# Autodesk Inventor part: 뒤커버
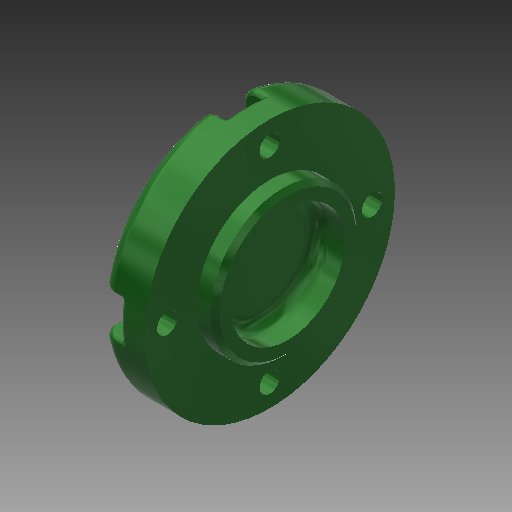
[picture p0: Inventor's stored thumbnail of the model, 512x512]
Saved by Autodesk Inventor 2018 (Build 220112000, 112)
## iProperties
Created: 2015-11
Part Number: 뒤커버
Material: 알루미늄 6061
Document SubType Name: Modeling
Designer: mduedu
Density: 1 g/cm^3
Appearance: 매끄러움 - 짙은 산림 녹색
Author: mduedu
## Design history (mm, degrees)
sketch "스케치1"
  geometry: L1 (-7, 0)-(7, 0); L2 (-7, 0)-(-7, 27.5); L3 (-7, 27.5)-(3, 27.5); L4 (3, 27.5)-(3, 16); L5 (3, 16)-(7, 16); L6 (7, 16)-(7, 0); 2 further points
  constraints: 12 end point, 3 perpendicular, 2 parallel, 1 coincident, 1 horizontal, 1 midpoint
  dimensions: "d0" = 14 distance of L1.start L1.end; "d1" = 55 diameter of L3 L1; "d2" = 4 distance of L4.end L5.end; "d3" = 32 diameter of L5 L1
revolve "회전1" sketch "스케치1" stored, may be unused: angle "d4" = 90 deg
hole "구멍1" diameter "d7" = 25; stored, may be unused: countersink angle "d11" = 90 deg, drill point angle "d13" = 0 deg; dims "d8" = 6, "d9" = 4, "d10" = 2, "d12" = 6, "d61" = 10, "d62" = 10
fillet "모깎기2" dims "d36" = 3
fillet "모깎기3" dims "d37" = 3
sketch "스케치2" dims "d39" = 45
  geometry: C1 r 12.846 at (0, 0) reference; C2 r 24.5 at (0, 0) reference; 6 further points
  constraints: 2 vertical alignment, 1 coincident, 7 other
  dimensions: "d42" = 360 deg dimension on point (0, 0) point (0, 22.5) (derived)
sketch "스케치3"
  geometry: 8 further points
  constraints: 4 coincident
hole "구멍4" sketch "스케치3" at (-22.5, 0), (0, -22.5), (22.5, 0), (0, 22.5) diameter "d44" = 4.5; stored, may be unused: countersink angle "d48" = 90 deg, drill point angle "d50" = 0 deg; dims "d45" = 6, "d46" = 8, "d47" = 4.6, "d49" = 8
sketch "스케치4"
  geometry: L1 (-4, 0)-(-4, -4.708); L2 (4, 0)-(4, -4.708); A1 r 4 centre (0, 0) between (-4, 0) and (4, 0) reference; A2 r 27.5 centre (0, 22.5) between (-4, -4.708) and (4, -4.708) reference; 3 further points
  constraints: 4 end point, 4 point on circle, 2 tangent, 1 parallel, 1 vertical
extrude "돌출1" cut sketch "스케치4" extent not by distance; stored distance "d51" = 0; taper "d52" = 0 deg
fillet "모깎기5" dims "d56" = 0.3
fillet "모깎기6" dims "d57" = 1
chamfer "모따기2" distance "d63" = 1; stored, may be unused: second distance "d64" = 2, angle "d65" = 45 deg
node "솔리드1"
pattern_circular "원형 패턴1" dims angle "d54" = 360 deg
